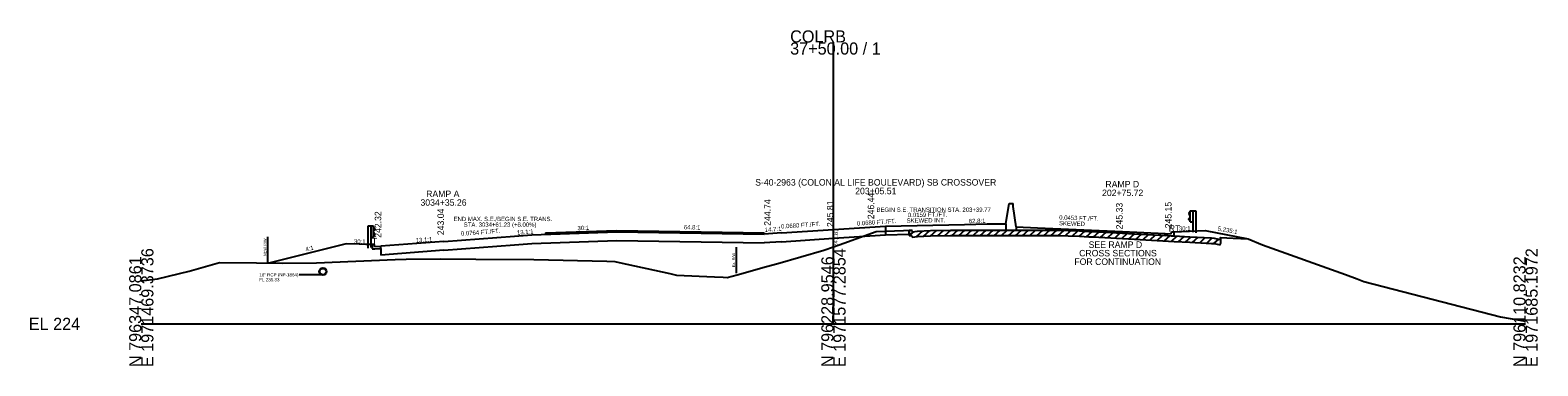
# Model space of a CAD drawing. Extents: x -26 to 1971766, y -10 to 796432.
# Drawn here: x -25.7 to 322.8, y 1990.3 to 2067.9 of the extents above; entities that cross this region are included whole.
import ezdxf

# ---------------------------------------------------------------- set-up
doc = ezdxf.new("R2010")
doc.units = 0
for name, color, linetype in [('BR_AUTO DIMENSION', 7, 'Continuous'), ('BR_BORDER LINES', 7, 'Continuous'), ('BR_CENTER LINE BASELINE', 7, 'Continuous'), ('BR_CENTER LINES', 7, 'Continuous'), ('BR_CONCRETE', 7, 'Continuous'), ('BR_DETAILS', 7, 'Continuous'), ('BR_PRESTRESSED BEAM', 7, 'Continuous'), ('BR_REBAR', 7, 'Continuous'), ('BR_TABLE LINES', 7, 'Continuous'), ('Default', 7, 'Continuous'), ('Level 31', 7, 'Continuous'), ('MISCELLANEOUS', 7, 'Continuous'), ('North Arrow', 7, 'Continuous'), ('RD_EX_Conc', 7, 'Continuous'), ('RD_EX_Road', 7, 'Continuous'), ('RD_HC_CL', 7, 'Continuous'), ('RD_HC_CL_Rel', 7, 'Continuous'), ('RD_PD_ALT1_TrvlWay', 7, 'Continuous'), ('RD_PD_ALT2_TnTmp', 7, 'Continuous'), ('RD_PD_CstnLmt', 7, 'Continuous'), ('RD_PD_Final_LnLine', 7, 'Continuous'), ('RD_PD_FOC', 7, 'Continuous'), ('RD_PD_GR', 7, 'Continuous'), ('RD_PD_MedBWall', 7, 'Continuous'), ('RD_PD_WallFill', 7, 'Continuous'), ('RD_SHT_IplotShp', 7, 'Continuous')]:
    doc.layers.add(name, color=color, linetype=linetype)

msp = doc.modelspace()

# ---------------------------------------------------------------- linework, layer by layer
at = {"layer": 'BR_AUTO DIMENSION'}
for p, q in [((160, 2000), (160, 2065.01)), ((0, 2000), (160, 2000)), ((160, 2000), (320, 2000))]:
    msp.add_line(p, q, dxfattribs=at)
at = {"layer": 'BR_BORDER LINES'}
msp.add_lwpolyline([(0, 2009.98), (3.75, 2010.38), (11.06, 2012.17), (18.04, 2014.16), (26.6, 2014.07), (32.6, 2014.04), (40.52, 2014.1), (58.65, 2014.84), (61.22, 2014.97), (69.08, 2015), (77.32, 2014.95), (90.76, 2014.89), (107.63, 2014.52), (109.45, 2014.44), (110.47, 2014.2), (122.19, 2011.6), (123.72, 2011.23), (132.51, 2010.85), (134.51, 2010.79), (135.44, 2010.75), (137.71, 2011.35), (144.54, 2013.23), (147.15, 2013.94), (157.8, 2017.04), (160, 2017.81), (162.4, 2018.67), (169.85, 2021.31), (176.23, 2021.58), (178.09, 2021.65), (178.2, 2021.25), (179.43, 2021.44), (182.43, 2021.56), (187.03, 2021.65), (188.17, 2021.67), (189.04, 2021.67), (202.98, 2021.63), (207.2, 2021.63), (211.39, 2021.65), (212.07, 2021.64), (214.3, 2021.59), (216.85, 2021.48), (219.04, 2021.38), (219.98, 2021.34), (229.56, 2020.84), (238.77, 2020.31), (242.39, 2020.13), (247.43, 2019.85), (248.03, 2019.82), (249.4, 2019.52), (249.51, 2019.92), (252.4, 2019.79), (255.87, 2019.64), (259.18, 2018.28), (278.39, 2011.4), (281.1, 2010.43), (282.64, 2009.79), (314.17, 2001.64), (320, 2000.6)], dxfattribs=at)
at = {"layer": 'BR_CENTER LINE BASELINE'}
for p, q in [((177.54, 2020.38), (177.54, 2021.63)), ((177.54, 2020.38), (178.09, 2020.4)), ((178.09, 2020.4), (178.2, 2020)), ((178.2, 2020), (179.43, 2020.19)), ((179.43, 2020.19), (182.43, 2020.31)), ((182.43, 2020.31), (187.03, 2020.4)), ((187.03, 2020.4), (188.17, 2020.42)), ((188.17, 2020.42), (189.04, 2020.42)), ((189.04, 2020.42), (202.98, 2020.38)), ((202.98, 2020.38), (207.2, 2020.38)), ((207.2, 2020.38), (211.39, 2020.4)), ((211.39, 2020.4), (212.07, 2020.39)), ((212.07, 2020.39), (214.3, 2020.34)), ((214.3, 2020.34), (216.85, 2020.23)), ((216.85, 2020.23), (219.04, 2020.13)), ((219.04, 2020.13), (219.98, 2020.09)), ((219.98, 2020.09), (229.56, 2019.59)), ((229.56, 2019.59), (238.77, 2019.06)), ((238.77, 2019.06), (242.39, 2018.88)), ((242.39, 2018.88), (247.43, 2018.6)), ((247.43, 2018.6), (248.03, 2018.57)), ((248.03, 2018.57), (249.4, 2018.27)), ((249.4, 2018.27), (249.49, 2018.58)), ((249.49, 2019.83), (249.49, 2018.58))]:
    msp.add_line(p, q, dxfattribs=at)
at = {"layer": 'BR_CENTER LINES'}
for q in [(47.38, 2018.52), (51.87, 2018.37)]:
    msp.add_line((53.38, 2018.32), q, dxfattribs=at)
at = {"layer": 'BR_DETAILS'}
for p, q in [((93.45, 2021.05), (109.91, 2021.6)), ((109.91, 2021.6), (144, 2021.07)), ((93.45, 2021.05), (93.45, 2020.72)), ((144, 2021.07), (144, 2020.74))]:
    msp.add_line(p, q, dxfattribs=at)
at = {"layer": 'BR_PRESTRESSED BEAM'}
for p, q in [((53.38, 2018.32), (53.38, 2017.32)), ((53.38, 2018.32), (53.38, 2017.32)), ((238.08, 2020.3), (236.66, 2020.38)), ((238.67, 2020.3), (238.08, 2020.3)), ((238.67, 2021.3), (238.67, 2020.3)), ((53.38, 2017.32), (53.97, 2017.32)), ((53.97, 2017.32), (55.39, 2017.41))]:
    msp.add_line(p, q, dxfattribs=at)
at = {"layer": 'BR_TABLE LINES'}
msp.add_line((137.5, 2017.72), (137.5, 2011.72), dxfattribs=at)
at = {"layer": 'Level 31'}
for p, q in [((180.82, 2020.25), (182.25, 2021.55)), ((182.45, 2020.31), (183.85, 2021.59)), ((184.09, 2020.34), (185.49, 2021.62)), ((185.73, 2020.38), (187.12, 2021.65)), ((187.37, 2020.41), (188.75, 2021.67)), ((189, 2020.42), (190.36, 2021.67)), ((190.64, 2020.42), (192, 2021.66)), ((192.28, 2020.41), (193.64, 2021.66)), ((193.92, 2020.41), (195.28, 2021.65)), ((195.55, 2020.4), (196.91, 2021.65)), ((197.19, 2020.4), (198.55, 2021.65)), ((198.83, 2020.39), (200.19, 2021.64)), ((200.46, 2020.39), (201.82, 2021.64)), ((202.1, 2020.39), (203.46, 2021.63)), ((203.74, 2020.38), (205.1, 2021.63)), ((205.38, 2020.38), (206.74, 2021.63)), ((207.01, 2020.38), (208.39, 2021.63)), ((208.65, 2020.39), (210.03, 2021.65)), ((210.29, 2020.4), (211.65, 2021.65)), ((211.92, 2020.39), (213.26, 2021.61)), ((213.56, 2020.36), (214.88, 2021.56)), ((215.2, 2020.3), (216.5, 2021.49)), ((177.54, 2020.38), (178.55, 2021.3)), ((179.18, 2020.15), (180.64, 2021.49)), ((216.84, 2020.23), (218.14, 2021.42)), ((218.47, 2020.16), (219.78, 2021.35)), ((220.11, 2020.09), (221.4, 2021.27)), ((221.75, 2020), (223.04, 2021.18)), ((223.39, 2019.91), (224.68, 2021.1)), ((225.02, 2019.83), (226.31, 2021.01)), ((226.66, 2019.74), (227.95, 2020.93)), ((228.3, 2019.66), (229.59, 2020.84)), ((229.93, 2019.57), (231.22, 2020.75)), ((231.57, 2019.48), (232.85, 2020.65)), ((233.21, 2019.38), (234.49, 2020.56)), ((234.85, 2019.28), (236.13, 2020.46)), ((236.48, 2019.19), (237.77, 2020.36)), ((238.12, 2019.09), (239.41, 2020.27)), ((239.76, 2019.01), (241.06, 2020.2)), ((241.4, 2018.93), (242.69, 2020.12)), ((243.03, 2018.85), (244.32, 2020.02)), ((244.67, 2018.75), (245.95, 2019.93)), ((246.31, 2018.66), (247.59, 2019.84)), ((247.94, 2018.57), (249.06, 2019.59))]:
    msp.add_line(p, q, dxfattribs=at)
at = {"layer": 'MISCELLANEOUS'}
for p, q in [((177.54, 2021.63), (178.09, 2021.65)), ((177.54, 2021.63), (177.54, 2020.7)), ((178.09, 2021.65), (178.2, 2021.25)), ((179.43, 2021.44), (182.43, 2021.56)), ((182.43, 2021.56), (187.03, 2021.65)), ((187.03, 2021.65), (188.17, 2021.67)), ((188.17, 2021.67), (189.04, 2021.67)), ((189.04, 2021.67), (196.17, 2021.65)), ((196.17, 2021.65), (199.85, 2021.64)), ((202.27, 2021.64), (207.18, 2021.63)), ((207.18, 2021.63), (211.39, 2021.65)), ((211.39, 2021.65), (212.35, 2021.63)), ((212.35, 2021.63), (214.3, 2021.59)), ((214.3, 2021.59), (216.85, 2021.48)), ((178.2, 2021.25), (179.43, 2021.44)), ((216.85, 2021.48), (219.04, 2021.38)), ((219.04, 2021.38), (219.98, 2021.34)), ((219.98, 2021.34), (229.56, 2020.84)), ((229.56, 2020.84), (236.66, 2020.43)), ((238.77, 2020.31), (239.61, 2020.27))]:
    msp.add_line(p, q, dxfattribs=at)
at = {"layer": 'North Arrow'}
for p, q in [((148, 2021.01), (160, 2021.81)), ((160, 2021.81), (172, 2022.61)), ((172, 2022.61), (190.28, 2022.99)), ((207.18, 2022.22), (226.84, 2021.33)), ((69.97, 2019.04), (86.24, 2020.3)), ((226.84, 2021.33), (236.66, 2020.88))]:
    msp.add_line(p, q, dxfattribs=at)
at = {"layer": 'RD_EX_Conc'}
for p, q in [((53.88, 2018.32), (53.38, 2018.32)), ((53.88, 2018.32), (53.38, 2018.32)), ((53.97, 2017.82), (53.88, 2018.32)), ((53.97, 2017.82), (53.88, 2018.32)), ((236.66, 2020.9), (236.66, 2020.88)), ((236.66, 2020.88), (238.08, 2020.8)), ((238.08, 2020.8), (238.17, 2021.3)), ((238.17, 2021.3), (238.67, 2021.3)), ((55.39, 2017.91), (53.97, 2017.82)), ((55.39, 2017.93), (55.39, 2017.91))]:
    msp.add_line(p, q, dxfattribs=at)
at = {"layer": 'RD_EX_Road'}
for p, q in [((172, 2022.61), (172, 2020.6)), ((69.97, 2017), (86.24, 2018.26)), ((86.24, 2018.26), (90.31, 2018.57)), ((90.31, 2018.57), (109.91, 2019.23)), ((109.91, 2019.23), (144, 2018.7)), ((148, 2018.97), (144, 2018.7)), ((148, 2018.97), (160, 2019.79)), ((160, 2019.78), (172, 2020.6)), ((172, 2020.6), (177.54, 2020.7)), ((236.66, 2020.88), (236.66, 2020.9)), ((236.66, 2020.38), (236.66, 2020.88)), ((55.39, 2017.91), (55.39, 2017.93)), ((55.39, 2017.41), (55.39, 2017.91)), ((55.39, 2017.41), (55.39, 2015.89)), ((69.97, 2017), (55.39, 2015.89))]:
    msp.add_line(p, q, dxfattribs=at)
at = {"layer": 'RD_HC_CL'}
for p, q in [((242.44, 2025.95), (242.17, 2025.51)), ((242.17, 2025.51), (242.17, 2025.4)), ((242.17, 2025.4), (242.44, 2024.96)), ((242.44, 2026.11), (243.1, 2026.11)), ((242.44, 2023.54), (242.44, 2026.11)), ((243.1, 2026.11), (243.77, 2026.11)), ((243.1, 2026.11), (243.1, 2021.17)), ((243.77, 2026.11), (243.77, 2021.06)), ((53.03, 2022.55), (52.36, 2022.55)), ((52.36, 2022.55), (52.36, 2017.5)), ((53.69, 2022.55), (53.03, 2022.55)), ((53.03, 2022.55), (53.03, 2017.61)), ((53.69, 2019.98), (53.69, 2022.55)), ((53.69, 2022.39), (53.96, 2021.95)), ((53.96, 2021.84), (53.69, 2021.4)), ((53.96, 2021.95), (53.96, 2021.84)), ((242.17, 2024.25), (242.44, 2024.69)), ((242.17, 2024.14), (242.17, 2024.25)), ((242.44, 2023.7), (242.17, 2024.14)), ((242.44, 2023.54), (243.1, 2023.54)), ((53.69, 2019.98), (53.03, 2019.98)), ((53.96, 2020.69), (53.69, 2021.13)), ((53.69, 2020.14), (53.96, 2020.58)), ((53.96, 2020.58), (53.96, 2020.69))]:
    msp.add_line(p, q, dxfattribs=at)
at = {"layer": 'RD_PD_CstnLmt'}
msp.add_line((29.17, 2020.1), (29.17, 2014.1), dxfattribs=at)
at = {"layer": 'RD_PD_Final_LnLine'}
for p, q in [((238.67, 2021.3), (245.92, 2021.54)), ((245.92, 2021.54), (255.87, 2019.64)), ((47.38, 2018.52), (29.52, 2014.06))]:
    msp.add_line(p, q, dxfattribs=at)
at = {"layer": 'RD_PD_FOC'}
msp.add_line((41.49, 2011.33), (36.49, 2011.33), dxfattribs=at)
for radius in [0.85, 0.75]:
    msp.add_circle((41.99, 2012.08), radius, dxfattribs=at)
at = {"layer": 'RD_PD_GR'}
for p, q in [((199.85, 2023.15), (200.6, 2027.81)), ((200.6, 2027.81), (201.52, 2027.81)), ((201.52, 2027.11), (201.52, 2027.81)), ((202.27, 2022.44), (201.52, 2027.11)), ((199.85, 2023.15), (199.85, 2021.64)), ((199.85, 2021.64), (202.27, 2021.64)), ((202.27, 2022.44), (202.27, 2021.64))]:
    msp.add_line(p, q, dxfattribs=at)
at = {"layer": 'RD_PD_MedBWall'}
for p, q in [((190.28, 2022.99), (195.52, 2023.08)), ((195.52, 2023.08), (199.85, 2023.15)), ((202.27, 2022.44), (207.18, 2022.22)), ((69.97, 2019.04), (55.39, 2017.93)), ((86.24, 2020.3), (90.31, 2020.61)), ((90.31, 2020.61), (109.91, 2021.27)), ((109.91, 2021.27), (144, 2020.74)), ((148, 2021.01), (144, 2020.74))]:
    msp.add_line(p, q, dxfattribs=at)

# ---------------------------------------------------------------- texts
at = {"layer": 'BR_AUTO DIMENSION'}
for s, p in [('COLRB', (150, 2065.01)), ('37+50.00 / 1', (150, 2062.21)), ('EL 224', (-26, 1998.6))]:
    msp.add_text(s, height=2.8, dxfattribs=at).set_placement(p)
for s, p in [('N 796347.0861', (0, 1990)), ('E 1971469.3736', (2.8, 1990)), ('N 796228.9546', (160, 1990)), ('E 1971577.2854', (162.8, 1990)), ('N 796110.8232', (320, 1990)), ('E 1971685.1972', (322.8, 1990))]:
    msp.add_text(s, height=2.8, rotation=90, dxfattribs=at).set_placement(p)
at = {"layer": 'BR_CONCRETE'}
for s, rotation, p in [('0.0159 FT./FT.', 0.912, (177.23, 2024.66)), ('0.0453 FT./FT.', 357.9735, (212.18, 2024.11)), ('0.0764 FT./FT.', 4.369, (73.92, 2020.34)), ('13.1:1', 4.369, (86.88, 2020.6)), ('30:1', 2.3185, (100.85, 2021.62)), ('64.8:1', 359.1162, (125.41, 2021.85)), ('0.0680 FT./FT.', 3.8901, (147.93, 2022.01)), ('0.0680 FT./FT.', 3.8901, (165.46, 2022.69)), ('SKEWED INT.', 0.912, (176.94, 2023.35)), ('62.8:1', 0.912, (191.31, 2023.26)), ('SKEWED', 357.9735, (212.13, 2022.8)), ('30:1', 1.1458, (239.88, 2021.51)), ('5.235:1', 349.1845, (248.8, 2021.59)), ('4:1', 14.0362, (38.07, 2016.71)), ('30:1', 359.1385, (49.16, 2018.56))]:
    msp.add_text(s, height=1, rotation=rotation, dxfattribs=at).set_placement(p)
at = {"layer": 'BR_REBAR'}
for s, p in [('RT', (237.52, 2021.3)), ('LT', (52.18, 2018.32))]:
    msp.add_text(s, height=1.5, dxfattribs=at).set_placement(p)
at = {"layer": 'BR_TABLE LINES'}
msp.add_text('Ex. R/W ', height=0.65, rotation=90, dxfattribs=at).set_placement((137.25, 2013.1))
at = {"layer": 'Default'}
for s, p in [('244.74', (145.5, 2022.66)), ('242.32', (55.47, 2019.88))]:
    msp.add_text(s, height=1.5, rotation=90, dxfattribs=at).set_placement(p)
at = {"layer": 'RD_HC_CL_Rel'}
for s, p in [('246.44', (169.42, 2024.17)), ('243.04', (69.97, 2020.49)), (' 245.81', (160, 2021.81)), (' 245.33', (226.84, 2021.28)), (' 245.15', (238.16, 2021.51))]:
    msp.add_text(s, height=1.5, rotation=90, dxfattribs=at).set_placement(p)
at = {"layer": 'RD_PD_ALT1_TrvlWay'}
for s, rotation, p in [('14.7:1', 3.8901, (144.17, 2021.23)), ('13.1:1', 4.3615, (63.48, 2018.79))]:
    msp.add_text(s, height=1, rotation=rotation, dxfattribs=at).set_placement(p)
at = {"layer": 'RD_PD_ALT2_TnTmp'}
for s, height, p in [('BEGIN S.E. TRANSITION STA. 203+39.77', 1, (169.95, 2025.88)), ('END MAX. S.E./BEGIN S.E. TRANS.', 1, (72.19, 2023.74)), (' STA. 3034+61.23 (+8.00%)', 1, (74.15, 2022.43)), ('SEE RAMP D', 1.5, (219, 2017.55)), ('FOR CONTINUATION', 1.5, (215.7, 2013.62)), ('CROSS SECTIONS ', 1.5, (216.81, 2015.59))]:
    msp.add_text(s, height=height, dxfattribs=at).set_placement(p)
at = {"layer": 'RD_PD_CstnLmt'}
msp.add_text('NEW R/W ', height=0.65, rotation=90, dxfattribs=at).set_placement((28.9, 2015.66))
at = {"layer": 'RD_PD_FOC'}
for s, p in [('18" RCP (NP-1864)', (27.28, 2010.96)), ('FL 235.33', (27.28, 2009.83))]:
    msp.add_text(s, height=0.75, dxfattribs=at).set_placement(p)
at = {"layer": 'RD_PD_WallFill'}
for s, p in [('S-40-2963 (COLONIAL LIFE BOULEVARD) SB CROSSOVER', (141.91, 2031.95)), ('RAMP D', (222.87, 2031.53)), ('3034+35.26', (64.54, 2027.29)), ('RAMP A', (65.85, 2029.29)), ('203+05.51', (165.03, 2029.95)), ('202+75.72', (222.1, 2029.53))]:
    msp.add_text(s, height=1.5, dxfattribs=at).set_placement(p)
at = {"layer": 'RD_SHT_IplotShp'}
msp.add_text('241.81', height=1, rotation=90, dxfattribs=at).set_placement((161, 2017.81))

doc.saveas('drawing.dxf')
